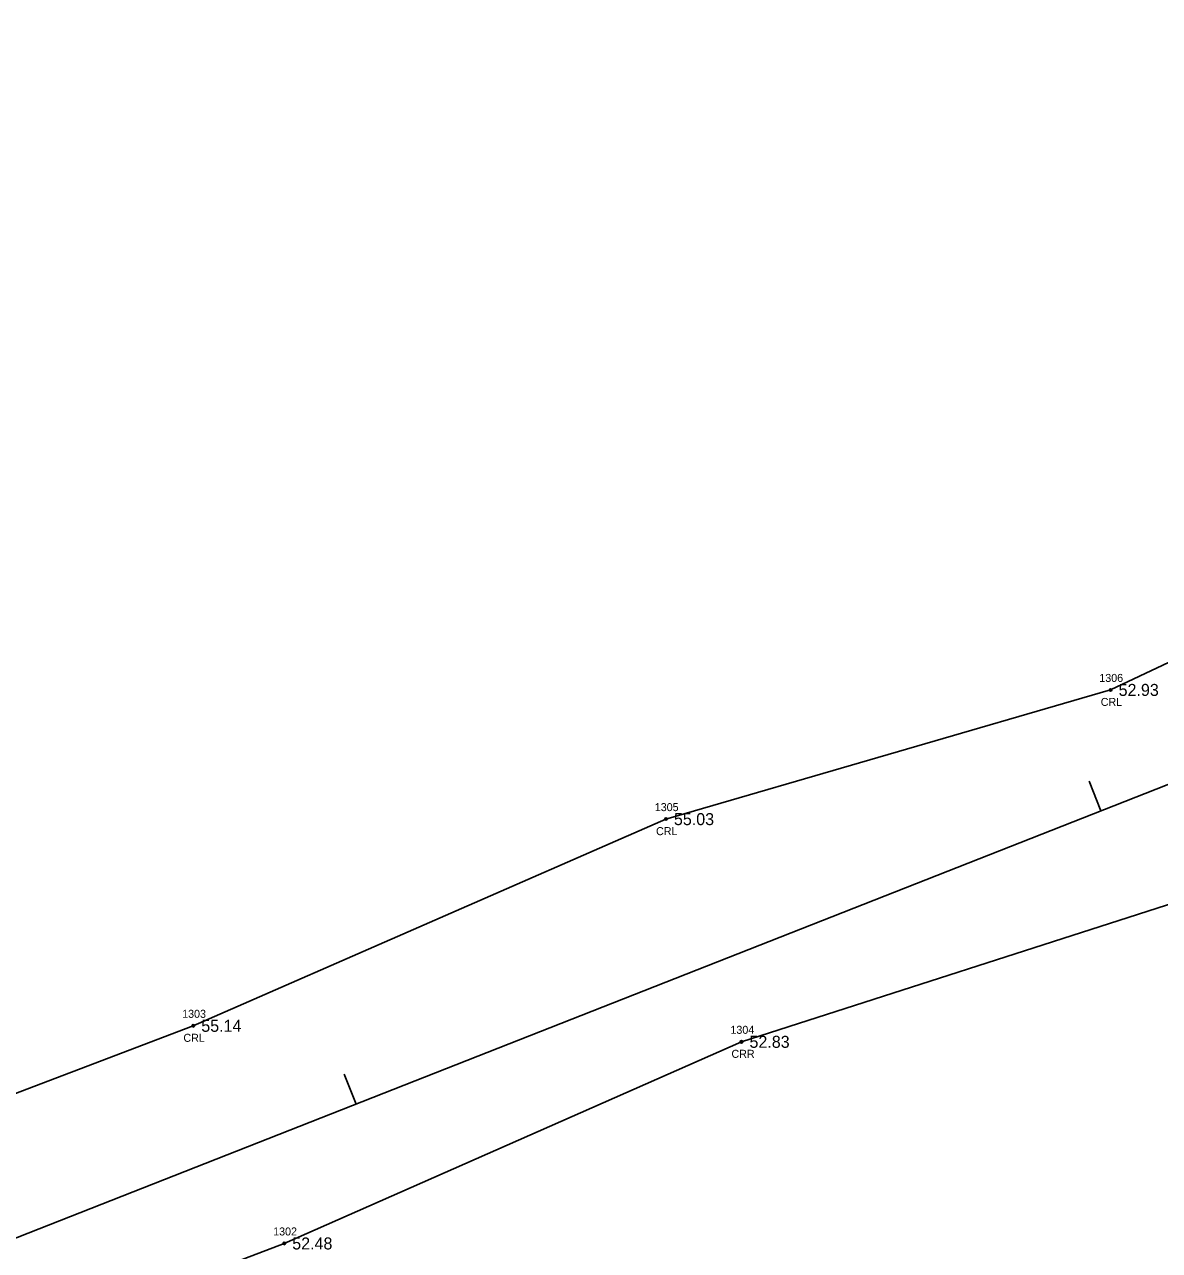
# Model space of a CAD drawing. Extents: x 2396531 to 2397633, y 770203 to 772837.
# Drawn here: x 2397094.6 to 2397236.4, y 771396.5 to 771549.6 of the extents above; entities that cross this region are included whole.
import ezdxf

# ---------------------------------------------------------------- set-up
doc = ezdxf.new("R2010")
doc.units = 0
for name, color, linetype in [('RD_EX_H2O', 7, 'Continuous'), ('RD_EX_H2O_txCode', 7, 'Continuous'), ('RD_EX_TX_H2O_ELEV', 7, 'Continuous'), ('RD_HC_Cl', 7, 'Continuous'), ('RD_HC_Data_Tic', 7, 'Continuous'), ('RD_SMD_Locator', 7, 'Continuous')]:
    doc.layers.add(name, color=color, linetype=linetype)

msp = doc.modelspace()

# ---------------------------------------------------------------- linework, layer by layer
at = {"layer": 'RD_EX_H2O'}
for points in [[(2397026.41, 771393.39), (2397070.16, 771405.14), (2397085.18, 771412.94), (2397115.64, 771424.52), (2397174.69, 771450.34), (2397230.25, 771466.48), (2397283.24, 771491.48), (2397342.91, 771519.42), (2397408.89, 771536.24), (2397447.46, 771546.47), (2397469.5, 771549.6), (2397497.19, 771541.27), (2397541.1, 771500.79)], [(2397041.52, 771355.95), (2397076.78, 771367.04), (2397074.45, 771374.78), (2397101.55, 771387.62), (2397127, 771397.33), (2397184.13, 771422.52), (2397239.58, 771440.33), (2397295.12, 771461.42), (2397353.86, 771487.36), (2397417.93, 771512.91), (2397437.51, 771516.93), (2397483.94, 771516.4), (2397526.36, 771480.62)]]:
    msp.add_lwpolyline(points, dxfattribs=at)
at = {"layer": 'RD_HC_Cl'}
msp.add_line((2396577.63, 771195.09), (2397449.32, 771538.02), dxfattribs=at)
at = {"layer": 'RD_HC_Data_Tic'}
for p, q in [((2397229.03, 771451.36), (2397227.57, 771455.08)), ((2397135.97, 771414.75), (2397134.51, 771418.47))]:
    msp.add_line(p, q, dxfattribs=at)
at = {"layer": 'RD_SMD_Locator'}
for centre in [(2397230.25, 771466.48), (2397174.69, 771450.34), (2397115.64, 771424.52), (2397184.13, 771422.52), (2397127, 771397.33)]:
    msp.add_circle(centre, 0.15, dxfattribs=at)

# ---------------------------------------------------------------- texts
at = {"layer": 'RD_EX_H2O_txCode'}
for s, p in [('1306', (2397228.84, 771467.48)), ('CRL', (2397229.02, 771464.48)), ('1305', (2397173.3, 771451.34)), ('CRL', (2397173.46, 771448.34)), ('1303', (2397114.25, 771425.52)), ('CRL', (2397114.41, 771422.52)), ('1304', (2397182.75, 771423.52)), ('CRR', (2397182.88, 771420.52)), ('1302', (2397125.62, 771398.33))]:
    msp.add_text(s, height=1, dxfattribs=at).set_placement(p)
at = {"layer": 'RD_EX_TX_H2O_ELEV'}
for s, p in [('52.93', (2397231.25, 771465.73)), ('55.03', (2397175.69, 771449.59)), ('55.14', (2397116.64, 771423.77)), ('52.83', (2397185.13, 771421.77)), ('52.48', (2397128, 771396.58))]:
    msp.add_text(s, height=1.5, dxfattribs=at).set_placement(p)

doc.saveas('drawing.dxf')
